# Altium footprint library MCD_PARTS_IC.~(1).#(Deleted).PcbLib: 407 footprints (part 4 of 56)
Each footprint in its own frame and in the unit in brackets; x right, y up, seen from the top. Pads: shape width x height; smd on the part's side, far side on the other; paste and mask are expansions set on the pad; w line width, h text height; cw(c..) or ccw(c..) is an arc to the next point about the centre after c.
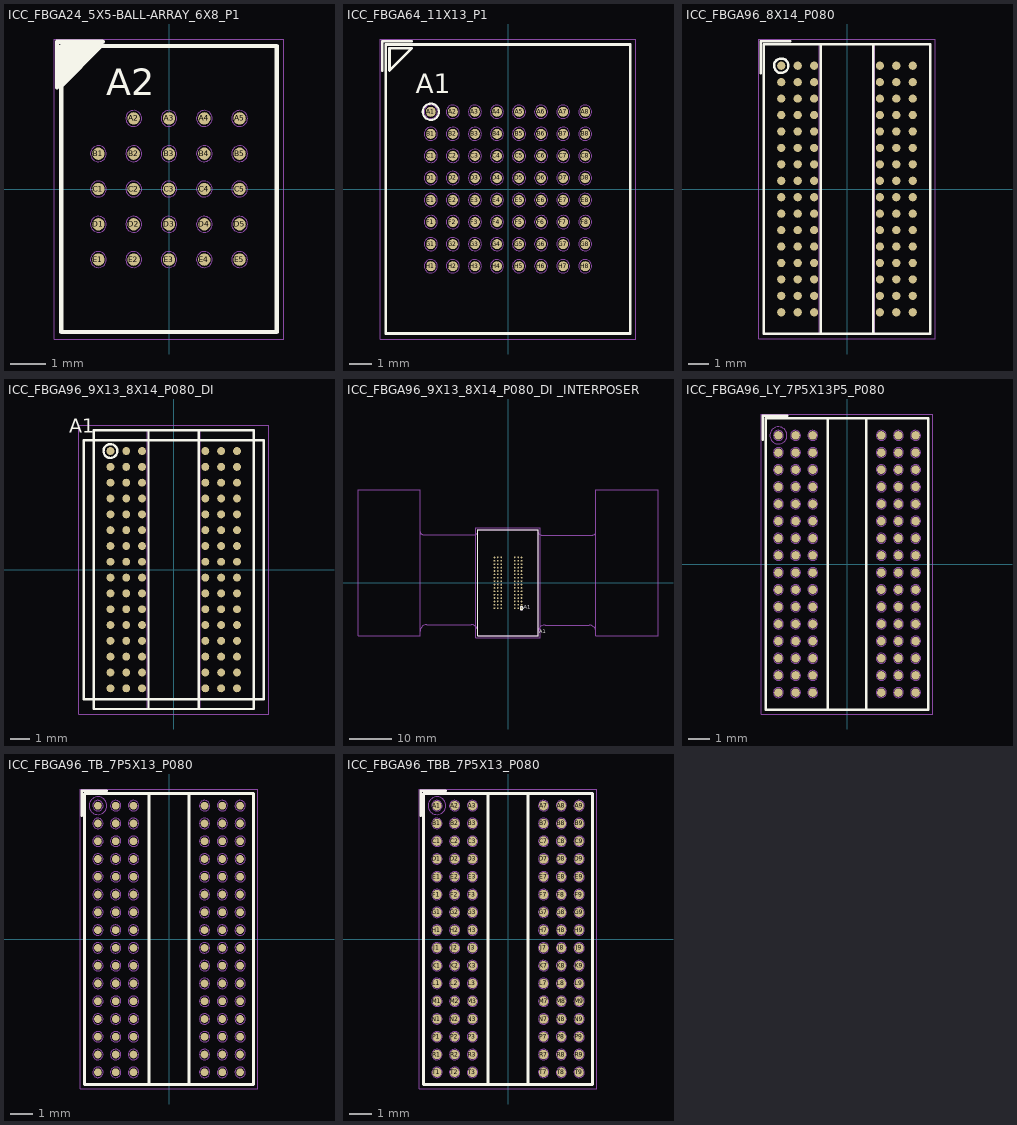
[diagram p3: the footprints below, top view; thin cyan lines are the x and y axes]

## ICC_FBGA24_5X5-BALL-ARRAY_6X8_P1 [mm] "MCD-01824"
height 1
pads (24):
  round 0.35 smd mask+0.05: A2(-1,2) A3(0,2) A4(1,2) A5(2,2) B1(-2,1) B2(-1,1) B3(0,1) B4(1,1) B5(2,1) C1(-2,0) C2(-1,0) C3(0,0) C4(1,0) C5(2,0) D1(-2,-1) D2(-1,-1) D3(0,-1) D4(1,-1) D5(2,-1) E1(-2,-2) E2(-1,-2) E3(0,-2) E4(1,-2) E5(2,-2)
Top Overlay:
  lines w0.12: -3.175,2.875 -3.175,4.175 -1.875,4.175 ; -3.05,2.925 -1.925,4.05 ; -3.05,3.025 -2.025,4.05 ; -3.05,3.175 -2.175,4.05 ; -3.05,3.325 -2.325,4.05 ; -3.05,3.475 -2.475,4.05 ; -3.05,3.625 -2.625,4.05 ; -3.05,3.775 -2.775,4.05 ; -3.05,3.9 -2.9,4.05 ; -3.05,-4.05 -3.05,4.05 3.05,4.05 3.05,-4.05 -3.05,-4.05
  text "A2" at -1.775,2.4 h1.3
M14-Top Assembly:
  circle w0.01: c-1,2 r0.225
  circle w0.01: c0,2 r0.225
  circle w0.01: c1,2 r0.225
  circle w0.01: c2,2 r0.225
  circle w0.01: c2,1 r0.225
  circle w0.01: c1,1 r0.225
  circle w0.01: c0,1 r0.225
  circle w0.01: c-1,1 r0.225
  circle w0.01: c-2,1 r0.225
  circle w0.01: c2,0 r0.225
  circle w0.01: c1,0 r0.225
  circle w0.01: c0,0 r0.225
  circle w0.01: c-1,0 r0.225
  circle w0.01: c-2,0 r0.225
  circle w0.01: c2,-1 r0.225
  circle w0.01: c1,-1 r0.225
  circle w0.01: c0,-1 r0.225
  circle w0.01: c-1,-1 r0.225
  circle w0.01: c-2,-1 r0.225
  circle w0.01: c2,-2 r0.225
  circle w0.01: c1,-2 r0.225
  circle w0.01: c0,-2 r0.225
  circle w0.01: c-1,-2 r0.225
  circle w0.01: c-2,-2 r0.225
  lines w0.01: -3.05,2.925 -1.925,4.05 -3.037,2.937 ; -3.05,-4.05 3.05,-4.05 3.05,4.05 -3.05,4.05 -3.05,-4.05
  text "'.Designator'" at -2,2.7 h0.75
  text "A2" at -1.424,1.795 h0.75
  text "E1" at -2.304,-2.205 h0.75
  text "D1" at -2.319,-1.205 h0.75
  text "C1" at -2.36,-0.205 h0.75
  text "B1" at -2.319,0.795 h0.75
  text "A5" at 1.601,1.795 h0.75
  text "A4" at 0.594,1.82 h0.75
  text "A3" at -0.424,1.795 h0.75
M16-Top Courtyard:
  lines w0.01: -3.25,-4.25 3.25,-4.25 3.25,4.25 -3.25,4.25 -3.25,-4.25
3D body "ICC_BGA24_5X5-BALL-ARRAY_6X8_P1.STEP": height 0.96, standoff -0.04, extent -3,-4 3,4
3D body: height 1, standoff 0, extent -3.055,-4.055 3.055,4.055

## ICC_FBGA64_11X13_P1 [mm] "IPC"
height 1.4
pads (64):
  round 0.45 smd mask+0.05: A1(-3.5,3.5) A2(-2.5,3.5) A3(-1.5,3.5) A4(-0.5,3.5) A5(0.5,3.5) A6(1.5,3.5) A7(2.5,3.5) A8(3.5,3.5) B1(-3.5,2.5) B2(-2.5,2.5) B3(-1.5,2.5) B4(-0.5,2.5) B5(0.5,2.5) B6(1.5,2.5) B7(2.5,2.5) B8(3.5,2.5) C1(-3.5,1.5) C2(-2.5,1.5) C3(-1.5,1.5) C4(-0.5,1.5) C5(0.5,1.5) C6(1.5,1.5) C7(2.5,1.5) C8(3.5,1.5) D1(-3.5,0.5) D2(-2.5,0.5) D3(-1.5,0.5) D4(-0.5,0.5) D5(0.5,0.5) D6(1.5,0.5) D7(2.5,0.5) D8(3.5,0.5) E1(-3.5,-0.5) E2(-2.5,-0.5) E3(-1.5,-0.5) E4(-0.5,-0.5) E5(0.5,-0.5) E6(1.5,-0.5) E7(2.5,-0.5) E8(3.5,-0.5) F1(-3.5,-1.5) F2(-2.5,-1.5) F3(-1.5,-1.5) F4(-0.5,-1.5) F5(0.5,-1.5) F6(1.5,-1.5) F7(2.5,-1.5) F8(3.5,-1.5) G1(-3.5,-2.5) G2(-2.5,-2.5) G3(-1.5,-2.5) G4(-0.5,-2.5) G5(0.5,-2.5) G6(1.5,-2.5) G7(2.5,-2.5) G8(3.5,-2.5) H1(-3.5,-3.5) H2(-2.5,-3.5) H3(-1.5,-3.5) H4(-0.5,-3.5) H5(0.5,-3.5) H6(1.5,-3.5) H7(2.5,-3.5) H8(3.5,-3.5)
Top Overlay:
  circle w0.1: c-3.5,3.5 r0.37
  lines w0.12: -5.7,5.375 -5.7,6.7 -4.375,6.7 ; -5.55,-6.55 5.55,-6.55 5.55,6.55 -5.55,6.55 -5.55,-6.55 ; -5.375,5.375 -4.375,6.375 -5.375,6.375 -5.375,5.375
  text "A1" at -4.175,4.05 h1.5
M14-Top Assembly:
  circle w0.01: c-3.5,-0.5 r0.3
  circle w0.01: c-2.5,-0.5 r0.3
  circle w0.01: c-1.5,-0.5 r0.3
  circle w0.01: c-0.5,-0.5 r0.3
  circle w0.01: c0.5,-0.5 r0.3
  circle w0.01: c1.5,-0.5 r0.3
  circle w0.01: c2.5,-0.5 r0.3
  circle w0.01: c3.5,-0.5 r0.3
  circle w0.01: c3.5,-1.5 r0.3
  circle w0.01: c2.5,-1.5 r0.3
  circle w0.01: c1.5,-1.5 r0.3
  circle w0.01: c0.5,-1.5 r0.3
  circle w0.01: c-0.5,-1.5 r0.3
  circle w0.01: c-1.5,-1.5 r0.3
  circle w0.01: c-2.5,-1.5 r0.3
  circle w0.01: c-3.5,-1.5 r0.3
  circle w0.01: c3.5,-2.5 r0.3
  circle w0.01: c2.5,-2.5 r0.3
  circle w0.01: c1.5,-2.5 r0.3
  circle w0.01: c0.5,-2.5 r0.3
  circle w0.01: c-0.5,-2.5 r0.3
  circle w0.01: c-1.5,-2.5 r0.3
  circle w0.01: c-2.5,-2.5 r0.3
  circle w0.01: c-3.5,-2.5 r0.3
  circle w0.01: c3.5,-3.5 r0.3
  circle w0.01: c2.5,-3.5 r0.3
  circle w0.01: c1.5,-3.5 r0.3
  circle w0.01: c0.5,-3.5 r0.3
  circle w0.01: c-0.5,-3.5 r0.3
  circle w0.01: c-1.5,-3.5 r0.3
  circle w0.01: c-2.5,-3.5 r0.3
  circle w0.01: c-3.5,-3.5 r0.3
  circle w0.01: c-3.5,0.5 r0.3
  circle w0.01: c-2.5,0.5 r0.3
  circle w0.01: c-1.5,0.5 r0.3
  circle w0.01: c-0.5,0.5 r0.3
  circle w0.01: c0.5,0.5 r0.3
  circle w0.01: c1.5,0.5 r0.3
  circle w0.01: c2.5,0.5 r0.3
  circle w0.01: c3.5,0.5 r0.3
  circle w0.01: c-3.5,1.5 r0.3
  circle w0.01: c-2.5,1.5 r0.3
  circle w0.01: c-1.5,1.5 r0.3
  circle w0.01: c-0.5,1.5 r0.3
  circle w0.01: c0.5,1.5 r0.3
  circle w0.01: c1.5,1.5 r0.3
  circle w0.01: c2.5,1.5 r0.3
  circle w0.01: c3.5,1.5 r0.3
  circle w0.01: c-3.5,2.5 r0.3
  circle w0.01: c-2.5,2.5 r0.3
  circle w0.01: c-1.5,2.5 r0.3
  circle w0.01: c-0.5,2.5 r0.3
  circle w0.01: c0.5,2.5 r0.3
  circle w0.01: c1.5,2.5 r0.3
  circle w0.01: c2.5,2.5 r0.3
  circle w0.01: c3.5,2.5 r0.3
  circle w0.01: c3.5,3.5 r0.3
  circle w0.01: c2.5,3.5 r0.3
  circle w0.01: c1.5,3.5 r0.3
  circle w0.01: c0.5,3.5 r0.3
  circle w0.01: c-0.5,3.5 r0.3
  circle w0.01: c-1.5,3.5 r0.3
  circle w0.01: c-2.5,3.5 r0.3
  circle w0.01: c-3.5,3.5 r0.3
  lines w0.01: -5.55,-6.55 5.55,-6.55 5.55,6.55 -5.55,6.55 -5.55,-6.55 ; -5.375,5.375 -4.375,6.375 -5.375,6.375 -5.375,5.375
  text "'.Designator'" at -2,-0.5 h0.75
  text "A1" at -4,3.25 h1
M16-Top Courtyard:
  lines w0.01: -5.8,-6.8 -5.8,6.8 5.8,6.8 5.8,-6.8 -5.8,-6.8
3D body: height 1.4, standoff 0, extent -5.55,-6.55 5.55,6.55
3D body: height 1.41, standoff 1.4, extent -4.847,5.251 -4.25,5.85
3D body "FBGA64_11x13_P1.STEP": height 1.4, standoff 0, extent -5.5,-6.5 5.5,6.5

## ICC_FBGA96_8X14_P080 [mm]
height 1.2
pads (96):
  round 0.4 smd mask+0.05: A1(-3.2,6) A2(-2.4,6) A3(-1.6,6) A7(1.6,6) A8(2.4,6) A9(3.2,6) B1(-3.2,5.2) B2(-2.4,5.2) B3(-1.6,5.2) B7(1.6,5.2) B8(2.4,5.2) B9(3.2,5.2) C1(-3.2,4.4) C2(-2.4,4.4) C3(-1.6,4.4) C7(1.6,4.4) C8(2.4,4.4) C9(3.2,4.4) D1(-3.2,3.6) D2(-2.4,3.6) D3(-1.6,3.6) D7(1.6,3.6) D8(2.4,3.6) D9(3.2,3.6) E1(-3.2,2.8) E2(-2.4,2.8) E3(-1.6,2.8) E7(1.6,2.8) E8(2.4,2.8) E9(3.2,2.8) F1(-3.2,2) F2(-2.4,2) F3(-1.6,2) F7(1.6,2) F8(2.4,2) F9(3.2,2) G1(-3.2,1.2) G2(-2.4,1.2) G3(-1.6,1.2) G7(1.6,1.2) G8(2.4,1.2) G9(3.2,1.2) H1(-3.2,0.4) H2(-2.4,0.4) H3(-1.6,0.4) H7(1.6,0.4) H8(2.4,0.4) H9(3.2,0.4) J1(-3.2,-0.4) J2(-2.4,-0.4) J3(-1.6,-0.4) J7(1.6,-0.4) J8(2.4,-0.4) J9(3.2,-0.4) K1(-3.2,-1.2) K2(-2.4,-1.2) K3(-1.6,-1.2) K7(1.6,-1.2) K8(2.4,-1.2) K9(3.2,-1.2) L1(-3.2,-2) L2(-2.4,-2) L3(-1.6,-2) L7(1.6,-2) L8(2.4,-2) L9(3.2,-2) M1(-3.2,-2.8) M2(-2.4,-2.8) M3(-1.6,-2.8) M7(1.6,-2.8) M8(2.4,-2.8) M9(3.2,-2.8) N1(-3.2,-3.6) N2(-2.4,-3.6) N3(-1.6,-3.6) N7(1.6,-3.6) N8(2.4,-3.6) N9(3.2,-3.6) P1(-3.2,-4.4) P2(-2.4,-4.4) P3(-1.6,-4.4) P7(1.6,-4.4) P8(2.4,-4.4) P9(3.2,-4.4) R1(-3.2,-5.2) R2(-2.4,-5.2) R3(-1.6,-5.2) R7(1.6,-5.2) R8(2.4,-5.2) R9(3.2,-5.2) T1(-3.2,-6) T2(-2.4,-6) T3(-1.6,-6) T7(1.6,-6) T8(2.4,-6) T9(3.2,-6)
Top Overlay:
  lines w0.12: -4.2,5.625 -4.2,7.2 -2.75,7.2 ; -2.851,6.023 ccw(c-3.2,6) -2.85,6 ; -1.275,-7.05 -1.275,7.05 ; 1.275,-7.05 1.275,7.05 ; -4.05,-7.05 4.05,-7.05 4.05,7.05 -4.05,7.05 -4.05,-7.05
M14-Top Assembly:
  circle w0.01: c-3.2,6 r0.35
  lines w0.01: -1.35,-7.05 -1.35,7.05 ; 1.35,-7.05 1.35,7.05 ; -4.05,-7.05 4.05,-7.05 4.05,7.05 -4.05,7.05 -4.05,-7.05
  text "'.Designator'" at -2,-0.5 h0.75
  text "A1" at -3.55,5.8 h0.75
M16-Top Courtyard:
  lines w0.01: -4.3,-7.3 -3.975,-7.3 4.3,-7.3 4.3,7.3 -4.3,7.3 -4.3,-7.3
3D body: height 1.2, standoff 0, extent -4.055,-7.055 4.055,7.055
3D body "VFBGA96.STEP": height 1, standoff 0, extent -4,-6.5 4,6.5

## ICC_FBGA96_9X13_8X14_P080_DI [mm]
height 1.2
pads (96):
  round 0.4 smd mask+0.05: A1(-3.2,6) A2(-2.4,6) A3(-1.6,6) A7(1.6,6) A8(2.4,6) A9(3.2,6) B1(-3.2,5.2) B2(-2.4,5.2) B3(-1.6,5.2) B7(1.6,5.2) B8(2.4,5.2) B9(3.2,5.2) C1(-3.2,4.4) C2(-2.4,4.4) C3(-1.6,4.4) C7(1.6,4.4) C8(2.4,4.4) C9(3.2,4.4) D1(-3.2,3.6) D2(-2.4,3.6) D3(-1.6,3.6) D7(1.6,3.6) D8(2.4,3.6) D9(3.2,3.6) E1(-3.2,2.8) E2(-2.4,2.8) E3(-1.6,2.8) E7(1.6,2.8) E8(2.4,2.8) E9(3.2,2.8) F1(-3.2,2) F2(-2.4,2) F3(-1.6,2) F7(1.6,2) F8(2.4,2) F9(3.2,2) G1(-3.2,1.2) G2(-2.4,1.2) G3(-1.6,1.2) G7(1.6,1.2) G8(2.4,1.2) G9(3.2,1.2) H1(-3.2,0.4) H2(-2.4,0.4) H3(-1.6,0.4) H7(1.6,0.4) H8(2.4,0.4) H9(3.2,0.4) J1(-3.2,-0.4) J2(-2.4,-0.4) J3(-1.6,-0.4) J7(1.6,-0.4) J8(2.4,-0.4) J9(3.2,-0.4) K1(-3.2,-1.2) K2(-2.4,-1.2) K3(-1.6,-1.2) K7(1.6,-1.2) K8(2.4,-1.2) K9(3.2,-1.2) L1(-3.2,-2) L2(-2.4,-2) L3(-1.6,-2) L7(1.6,-2) L8(2.4,-2) L9(3.2,-2) M1(-3.2,-2.8) M2(-2.4,-2.8) M3(-1.6,-2.8) M7(1.6,-2.8) M8(2.4,-2.8) M9(3.2,-2.8) N1(-3.2,-3.6) N2(-2.4,-3.6) N3(-1.6,-3.6) N7(1.6,-3.6) N8(2.4,-3.6) N9(3.2,-3.6) P1(-3.2,-4.4) P2(-2.4,-4.4) P3(-1.6,-4.4) P7(1.6,-4.4) P8(2.4,-4.4) P9(3.2,-4.4) R1(-3.2,-5.2) R2(-2.4,-5.2) R3(-1.6,-5.2) R7(1.6,-5.2) R8(2.4,-5.2) R9(3.2,-5.2) T1(-3.2,-6) T2(-2.4,-6) T3(-1.6,-6) T7(1.6,-6) T8(2.4,-6) T9(3.2,-6)
Top Overlay:
  lines w0.12: -2.851,6.023 ccw(c-3.2,6) -2.85,6 ; -1.275,-7.05 -1.275,7.05 ; 1.275,-7.05 1.275,7.05 ; -4.55,-6.55 4.55,-6.55 4.55,6.55 -4.55,6.55 -4.55,-6.55 ; -4.05,-7.05 -4.05,7.05 4.05,7.05 4.05,-7.05 -4.05,-7.05
  text "A1" at -5.275,6.675 h1.2
M14-Top Assembly:
  circle w0.01: c-3.2,6 r0.35
  lines w0.01: -1.35,-7.05 -1.35,7.05 ; 1.35,-7.05 1.35,7.05 ; -4.55,-6.55 4.55,-6.55 4.55,6.55 -4.55,6.55 -4.55,-6.55 ; -4.05,-7.05 -4.05,7.05 4.05,7.05 4.05,-7.05 -4.05,-7.05
  text "9 x 13" at -4.15,-6.5 h0.6
  text "8 x 14" at -4.025,6.625 h0.6
  text "A1" at -3.575,5.775 h0.75
  text "'.Designator'" at -2,-0.5 h0.75
M16-Top Courtyard:
  lines w0.01: -4.8,-7.3 -4.8,7.3 4.8,7.3 4.8,-7.3 -4.8,-7.3
3D body: height 1, standoff 0, extent -4.55,-6.55 4.55,6.55
3D body: height 1.2, standoff 0, extent -4.05,-7.05 4.05,7.05

## ICC_FBGA96_9X13_8X14_P080_DI _INTERPOSER [mm] "INTERPOSER DDR3 MCI BBLA96BC-A01_DIMS"
height 2
pads (96):
  round 0.4 smd mask+0.05: A1(3.2,-6) A2(2.4,-6) A3(1.6,-6) A7(-1.6,-6) A8(-2.4,-6) A9(-3.2,-6) B1(3.2,-5.2) B2(2.4,-5.2) B3(1.6,-5.2) B7(-1.6,-5.2) B8(-2.4,-5.2) B9(-3.2,-5.2) C1(3.2,-4.4) C2(2.4,-4.4) C3(1.6,-4.4) C7(-1.6,-4.4) C8(-2.4,-4.4) C9(-3.2,-4.4) D1(3.2,-3.6) D2(2.4,-3.6) D3(1.6,-3.6) D7(-1.6,-3.6) D8(-2.4,-3.6) D9(-3.2,-3.6) E1(3.2,-2.8) E2(2.4,-2.8) E3(1.6,-2.8) E7(-1.6,-2.8) E8(-2.4,-2.8) E9(-3.2,-2.8) F1(3.2,-2) F2(2.4,-2) F3(1.6,-2) F7(-1.6,-2) F8(-2.4,-2) F9(-3.2,-2) G1(3.2,-1.2) G2(2.4,-1.2) G3(1.6,-1.2) G7(-1.6,-1.2) G8(-2.4,-1.2) G9(-3.2,-1.2) H1(3.2,-0.4) H2(2.4,-0.4) H3(1.6,-0.4) H7(-1.6,-0.4) H8(-2.4,-0.4) H9(-3.2,-0.4) J1(3.2,0.4) J2(2.4,0.4) J3(1.6,0.4) J7(-1.6,0.4) J8(-2.4,0.4) J9(-3.2,0.4) K1(3.2,1.2) K2(2.4,1.2) K3(1.6,1.2) K7(-1.6,1.2) K8(-2.4,1.2) K9(-3.2,1.2) L1(3.2,2) L2(2.4,2) L3(1.6,2) L7(-1.6,2) L8(-2.4,2) L9(-3.2,2) M1(3.2,2.8) M2(2.4,2.8) M3(1.6,2.8) M7(-1.6,2.8) M8(-2.4,2.8) M9(-3.2,2.8) N1(3.2,3.6) N2(2.4,3.6) N3(1.6,3.6) N7(-1.6,3.6) N8(-2.4,3.6) N9(-3.2,3.6) P1(3.2,4.4) P2(2.4,4.4) P3(1.6,4.4) P7(-1.6,4.4) P8(-2.4,4.4) P9(-3.2,4.4) R1(3.2,5.2) R2(2.4,5.2) R3(1.6,5.2) R7(-1.6,5.2) R8(-2.4,5.2) R9(-3.2,5.2) T1(3.2,6) T2(2.4,6) T3(1.6,6) T7(-1.6,6) T8(-2.4,6) T9(-3.2,6)
Top Overlay:
  lines w0.12: 2.85,-6 cw(c3.2,-6) 2.851,-6.023 ; 7.15,-12.5 7.15,-12.475 7.15,12.5 -7.15,12.5 -7.15,-12.5 7.125,-12.5 7.15,-12.5 ; 7.15,-12.5 7.15,-12.5
  text "A1" at 7.4,-12.325 h1.5
  text "A1" at 3.75,-6.425 h1.5
M7-Top Info:
  lines w0.01: -20.75,-11.4 cw(c-19.2,-11.45) -19.15,-9.9 -8.65,-9.9 cw(c-8.7,-11.45) -7.15,-11.5 ; -20.75,12.1 ccw(c-20.05,12.1) -20.05,11.4 -8.25,11.4 ; -7.15,12.1 cw(c-7.85,12.1) -7.85,11.4 -8.25,11.4 ; 7.15,-11.5 cw(c8.7,-11.55) 8.75,-10 19.25,-10 cw(c19.2,-11.55) 20.75,-11.6 ; 7.15,12 ccw(c7.85,12) 7.85,11.3 19.65,11.3 ; 20.75,12 cw(c20.05,12) 20.05,11.3 19.65,11.3 ; -8.25,11.4 -8.25,11.4 ; 7.125,-12.5 7.15,-12.5 ; 7.125,-12.5 7.15,-12.5 ; 7.125,-12.5 -7.15,-12.5 -7.15,12.5 7.15,12.5 7.15,-12.475 ; 7.15,-12.5 7.15,-12.5 ; 7.15,-12.5 7.15,-12.475 ; 7.15,-12.5 7.15,-12.475 ; 7.15,-12.5 7.15,-12.5 ; 19.65,11.3 19.65,11.3 ; -35.45,-12.5 -20.75,-12.5 -20.75,22 -35.45,22 -35.45,-12.5 ; 20.75,-12.5 20.75,22 35.45,22 35.45,-12.5 20.75,-12.5
  text "FLEX / AREA" at 11.225,-2 h1.5
  text "FLEX / AREA" at -17,-2 h1.5
M14-Top Assembly:
  circle w0.01: c3.2,-6 r0.35
  lines w0.01: 7.125,-12.5 -7.15,-12.5 -7.15,12.5 7.15,12.5 7.15,-12.475
  text "A1" at 2.85,-6.2 h0.75
  text "'.Designator'" at -2,-0.5 h0.75
M16-Top Courtyard:
  lines w0.01: -7.65,-13 7.65,-13 7.65,13 -7.65,13 -7.65,-13
3D body: height 3.3, standoff 2.3, extent 7.15,-11.475 20.75,11.975
3D body: height 3.3, standoff 2.3, extent -20.75,-11.375 -7.15,12.075
3D body: height 3.6, standoff 2, extent -7.15,-12.5 7.15,12.5
3D body: height 3.6, standoff 2, extent 20.75,-12.5 35.45,22
3D body "VFBGA96.STEP": height 4.6, standoff 3.6, extent -4,-6.5 4,6.5
3D body: height 2, standoff 0, extent -7.15,-12.5 7.15,12.5
3D body: height 3.6, standoff 2, extent -35.45,-12.5 -20.75,22

## ICC_FBGA96_LY_7P5X13P5_P080 [mm] "MCD-02322"
height 1.2
pads (96):
  round 0.4 smd mask+0.05: A1(-3.2,6) A2(-2.4,6) A3(-1.6,6) A7(1.6,6) A8(2.4,6) A9(3.2,6) B1(-3.2,5.2) B2(-2.4,5.2) B3(-1.6,5.2) B7(1.6,5.2) B8(2.4,5.2) B9(3.2,5.2) C1(-3.2,4.4) C2(-2.4,4.4) C3(-1.6,4.4) C7(1.6,4.4) C8(2.4,4.4) C9(3.2,4.4) D1(-3.2,3.6) D2(-2.4,3.6) D3(-1.6,3.6) D7(1.6,3.6) D8(2.4,3.6) D9(3.2,3.6) E1(-3.2,2.8) E2(-2.4,2.8) E3(-1.6,2.8) E7(1.6,2.8) E8(2.4,2.8) E9(3.2,2.8) F1(-3.2,2) F2(-2.4,2) F3(-1.6,2) F7(1.6,2) F8(2.4,2) F9(3.2,2) G1(-3.2,1.2) G2(-2.4,1.2) G3(-1.6,1.2) G7(1.6,1.2) G8(2.4,1.2) G9(3.2,1.2) H1(-3.2,0.4) H2(-2.4,0.4) H3(-1.6,0.4) H7(1.6,0.4) H8(2.4,0.4) H9(3.2,0.4) J1(-3.2,-0.4) J2(-2.4,-0.4) J3(-1.6,-0.4) J7(1.6,-0.4) J8(2.4,-0.4) J9(3.2,-0.4) K1(-3.2,-1.2) K2(-2.4,-1.2) K3(-1.6,-1.2) K7(1.6,-1.2) K8(2.4,-1.2) K9(3.2,-1.2) L1(-3.2,-2) L2(-2.4,-2) L3(-1.6,-2) L7(1.6,-2) L8(2.4,-2) L9(3.2,-2) M1(-3.2,-2.8) M2(-2.4,-2.8) M3(-1.6,-2.8) M7(1.6,-2.8) M8(2.4,-2.8) M9(3.2,-2.8) N1(-3.2,-3.6) N2(-2.4,-3.6) N3(-1.6,-3.6) N7(1.6,-3.6) N8(2.4,-3.6) N9(3.2,-3.6) P1(-3.2,-4.4) P2(-2.4,-4.4) P3(-1.6,-4.4) P7(1.6,-4.4) P8(2.4,-4.4) P9(3.2,-4.4) R1(-3.2,-5.2) R2(-2.4,-5.2) R3(-1.6,-5.2) R7(1.6,-5.2) R8(2.4,-5.2) R9(3.2,-5.2) T1(-3.2,-6) T2(-2.4,-6) T3(-1.6,-6) T7(1.6,-6) T8(2.4,-6) T9(3.2,-6)
Top Overlay:
  lines w0.12: -3.925,5.8 -3.925,6.925 -2.8,6.925 ; -0.9,-6.8 -0.9,6.8 ; 0.9,-6.8 0.9,6.8 ; -3.8,-6.8 3.8,-6.8 3.8,6.8 -3.8,6.8 -3.8,-6.8
M14-Top Assembly:
  circle w0.01: c-3.2,6 r0.235
  circle w0.01: c-2.4,6 r0.235
  circle w0.01: c-1.6,6 r0.235
  circle w0.01: c1.6,6 r0.235
  circle w0.01: c2.4,6 r0.235
  circle w0.01: c3.2,6 r0.235
  circle w0.01: c-3.2,5.2 r0.235
  circle w0.01: c-2.4,5.2 r0.235
  circle w0.01: c-1.6,5.2 r0.235
  circle w0.01: c1.6,5.2 r0.235
  circle w0.01: c2.4,5.2 r0.235
  circle w0.01: c3.2,5.2 r0.235
  circle w0.01: c-3.2,4.4 r0.235
  circle w0.01: c-2.4,4.4 r0.235
  circle w0.01: c-1.6,4.4 r0.235
  circle w0.01: c1.6,4.4 r0.235
  circle w0.01: c2.4,4.4 r0.235
  circle w0.01: c3.2,4.4 r0.235
  circle w0.01: c-3.2,3.6 r0.235
  circle w0.01: c-2.4,3.6 r0.235
  circle w0.01: c-1.6,3.6 r0.235
  circle w0.01: c1.6,3.6 r0.235
  circle w0.01: c2.4,3.6 r0.235
  circle w0.01: c3.2,3.6 r0.235
  circle w0.01: c-3.2,2.8 r0.235
  circle w0.01: c-2.4,2.8 r0.235
  circle w0.01: c-1.6,2.8 r0.235
  circle w0.01: c1.6,2.8 r0.235
  circle w0.01: c2.4,2.8 r0.235
  circle w0.01: c3.2,2.8 r0.235
  circle w0.01: c-3.2,2 r0.235
  circle w0.01: c-2.4,2 r0.235
  circle w0.01: c-1.6,2 r0.235
  circle w0.01: c1.6,2 r0.235
  circle w0.01: c2.4,2 r0.235
  circle w0.01: c3.2,2 r0.235
  circle w0.01: c-3.2,1.2 r0.235
  circle w0.01: c-2.4,1.2 r0.235
  circle w0.01: c-1.6,1.2 r0.235
  circle w0.01: c1.6,1.2 r0.235
  circle w0.01: c2.4,1.2 r0.235
  circle w0.01: c3.2,1.2 r0.235
  circle w0.01: c-3.2,0.4 r0.235
  circle w0.01: c-2.4,0.4 r0.235
  circle w0.01: c-1.6,0.4 r0.235
  circle w0.01: c1.6,0.4 r0.235
  circle w0.01: c2.4,0.4 r0.235
  circle w0.01: c3.2,0.4 r0.235
  circle w0.01: c-3.2,-6 r0.235
  circle w0.01: c-2.4,-6 r0.235
  circle w0.01: c-1.6,-6 r0.235
  circle w0.01: c1.6,-6 r0.235
  circle w0.01: c2.4,-6 r0.235
  circle w0.01: c3.2,-6 r0.235
  circle w0.01: c-3.2,-5.2 r0.235
  circle w0.01: c-2.4,-5.2 r0.235
  circle w0.01: c-1.6,-5.2 r0.235
  circle w0.01: c1.6,-5.2 r0.235
  circle w0.01: c2.4,-5.2 r0.235
  circle w0.01: c3.2,-5.2 r0.235
  circle w0.01: c-3.2,-4.4 r0.235
  circle w0.01: c-2.4,-4.4 r0.235
  circle w0.01: c-1.6,-4.4 r0.235
  circle w0.01: c1.6,-4.4 r0.235
  circle w0.01: c2.4,-4.4 r0.235
  circle w0.01: c3.2,-4.4 r0.235
  circle w0.01: c-3.2,-3.6 r0.235
  circle w0.01: c-2.4,-3.6 r0.235
  circle w0.01: c-1.6,-3.6 r0.235
  circle w0.01: c1.6,-3.6 r0.235
  circle w0.01: c2.4,-3.6 r0.235
  circle w0.01: c3.2,-3.6 r0.235
  circle w0.01: c-3.2,-2.8 r0.235
  circle w0.01: c-2.4,-2.8 r0.235
  circle w0.01: c-1.6,-2.8 r0.235
  circle w0.01: c1.6,-2.8 r0.235
  circle w0.01: c2.4,-2.8 r0.235
  circle w0.01: c3.2,-2.8 r0.235
  circle w0.01: c-3.2,-2 r0.235
  circle w0.01: c-2.4,-2 r0.235
  circle w0.01: c-1.6,-2 r0.235
  circle w0.01: c1.6,-2 r0.235
  circle w0.01: c2.4,-2 r0.235
  circle w0.01: c3.2,-2 r0.235
  circle w0.01: c-3.2,-1.2 r0.235
  circle w0.01: c-2.4,-1.2 r0.235
  circle w0.01: c-1.6,-1.2 r0.235
  circle w0.01: c1.6,-1.2 r0.235
  circle w0.01: c2.4,-1.2 r0.235
  circle w0.01: c3.2,-1.2 r0.235
  circle w0.01: c-3.2,-0.4 r0.235
  circle w0.01: c-2.4,-0.4 r0.235
  circle w0.01: c-1.6,-0.4 r0.235
  circle w0.01: c1.6,-0.4 r0.235
  circle w0.01: c2.4,-0.4 r0.235
  circle w0.01: c3.2,-0.4 r0.235
  circle w0.01: c-3.2,6 r0.4
  lines w0.01: -0.9,-6.8 -0.9,6.8 ; 0.9,-6.8 0.9,6.8 ; -3.8,-6.8 3.8,-6.8 3.8,6.8 -3.8,6.8 -3.8,-6.8
  text "A1" at -3.55,5.8 h0.75
  text "'.Designator'" at -2,-0.5 h0.75
M16-Top Courtyard:
  lines w0.01: -4,-7 4,-7 4,7 -4,7 -4,-7
3D body: height 1.2, standoff 0.28, extent -3.8,-6.8 3.8,6.8
3D body: height 0.36, standoff -0.04, extent 3.001,-6.197 3.4,-5.803
3D body: height 0.36, standoff -0.04, extent 2.201,-6.197 2.6,-5.803
3D body: height 0.36, standoff -0.04, extent 1.401,-6.197 1.8,-5.803
3D body: height 0.36, standoff -0.04, extent -1.799,-6.197 -1.4,-5.803
3D body: height 0.36, standoff -0.04, extent -2.599,-6.197 -2.2,-5.803
3D body: height 0.36, standoff -0.04, extent -3.399,-6.197 -3,-5.803
3D body: height 0.36, standoff -0.04, extent 3.001,-5.397 3.4,-5.003
3D body: height 0.36, standoff -0.04, extent 2.201,-5.397 2.6,-5.003
3D body: height 0.36, standoff -0.04, extent 1.401,-5.397 1.8,-5.003
3D body: height 0.36, standoff -0.04, extent -1.799,-5.397 -1.4,-5.003
3D body: height 0.36, standoff -0.04, extent -2.599,-5.397 -2.2,-5.003
3D body: height 0.36, standoff -0.04, extent -3.399,-5.397 -3,-5.003
3D body: height 0.36, standoff -0.04, extent 3.001,-4.597 3.4,-4.203
3D body: height 0.36, standoff -0.04, extent 2.201,-4.597 2.6,-4.203
3D body: height 0.36, standoff -0.04, extent 1.401,-4.597 1.8,-4.203
3D body: height 0.36, standoff -0.04, extent -1.799,-4.597 -1.4,-4.203
3D body: height 0.36, standoff -0.04, extent -2.599,-4.597 -2.2,-4.203
3D body: height 0.36, standoff -0.04, extent -3.399,-4.597 -3,-4.203
3D body: height 0.36, standoff -0.04, extent 3.001,-3.797 3.4,-3.403
3D body: height 0.36, standoff -0.04, extent 2.201,-3.797 2.6,-3.403
3D body: height 0.36, standoff -0.04, extent 1.401,-3.797 1.8,-3.403
3D body: height 0.36, standoff -0.04, extent -1.799,-3.797 -1.4,-3.403
3D body: height 0.36, standoff -0.04, extent -2.599,-3.797 -2.2,-3.403
3D body: height 0.36, standoff -0.04, extent -3.399,-3.797 -3,-3.403
3D body: height 0.36, standoff -0.04, extent 3.001,-2.997 3.4,-2.603
3D body: height 0.36, standoff -0.04, extent 2.201,-2.997 2.6,-2.603
3D body: height 0.36, standoff -0.04, extent 1.401,-2.997 1.8,-2.603
3D body: height 0.36, standoff -0.04, extent -1.799,-2.997 -1.4,-2.603
3D body: height 0.36, standoff -0.04, extent -2.599,-2.997 -2.2,-2.603
3D body: height 0.36, standoff -0.04, extent -3.399,-2.997 -3,-2.603
3D body: height 0.36, standoff -0.04, extent 3.001,-2.197 3.4,-1.803
3D body: height 0.36, standoff -0.04, extent 2.201,-2.197 2.6,-1.803
3D body: height 0.36, standoff -0.04, extent 1.401,-2.197 1.8,-1.803
3D body: height 0.36, standoff -0.04, extent -1.799,-2.197 -1.4,-1.803
3D body: height 0.36, standoff -0.04, extent -2.599,-2.197 -2.2,-1.803
3D body: height 0.36, standoff -0.04, extent -3.399,-2.197 -3,-1.803
3D body: height 0.36, standoff -0.04, extent 3.001,-1.397 3.4,-1.003
3D body: height 0.36, standoff -0.04, extent 2.201,-1.397 2.6,-1.003
3D body: height 0.36, standoff -0.04, extent 1.401,-1.397 1.8,-1.003
3D body: height 0.36, standoff -0.04, extent -1.799,-1.397 -1.4,-1.003
3D body: height 0.36, standoff -0.04, extent -2.599,-1.397 -2.2,-1.003
3D body: height 0.36, standoff -0.04, extent -3.399,-1.397 -3,-1.003
3D body: height 0.36, standoff -0.04, extent 3.001,-0.597 3.4,-0.203
3D body: height 0.36, standoff -0.04, extent 2.201,-0.597 2.6,-0.203
3D body: height 0.36, standoff -0.04, extent 1.401,-0.597 1.8,-0.203
3D body: height 0.36, standoff -0.04, extent -1.799,-0.597 -1.4,-0.203
3D body: height 0.36, standoff -0.04, extent -2.599,-0.597 -2.2,-0.203
3D body: height 0.36, standoff -0.04, extent -3.399,-0.597 -3,-0.203
3D body: height 0.36, standoff -0.04, extent 3.001,0.203 3.4,0.597
3D body: height 0.36, standoff -0.04, extent 2.201,0.203 2.6,0.597
3D body: height 0.36, standoff -0.04, extent 1.401,0.203 1.8,0.597
3D body: height 0.36, standoff -0.04, extent -1.799,0.203 -1.4,0.597
3D body: height 0.36, standoff -0.04, extent -2.599,0.203 -2.2,0.597
3D body: height 0.36, standoff -0.04, extent -3.399,0.203 -3,0.597
3D body: height 0.36, standoff -0.04, extent 3.001,1.003 3.4,1.397
3D body: height 0.36, standoff -0.04, extent 2.201,1.003 2.6,1.397
3D body: height 0.36, standoff -0.04, extent 1.401,1.003 1.8,1.397
3D body: height 0.36, standoff -0.04, extent -1.799,1.003 -1.4,1.397
3D body: height 0.36, standoff -0.04, extent -2.599,1.003 -2.2,1.397
3D body: height 0.36, standoff -0.04, extent -3.399,1.003 -3,1.397
3D body: height 0.36, standoff -0.04, extent 3.001,1.803 3.4,2.197
3D body: height 0.36, standoff -0.04, extent 2.201,1.803 2.6,2.197
3D body: height 0.36, standoff -0.04, extent 1.401,1.803 1.8,2.197
3D body: height 0.36, standoff -0.04, extent -1.799,1.803 -1.4,2.197
3D body: height 0.36, standoff -0.04, extent -2.599,1.803 -2.2,2.197
3D body: height 0.36, standoff -0.04, extent -3.399,1.803 -3,2.197
3D body: height 0.36, standoff -0.04, extent 3.001,2.603 3.4,2.997
3D body: height 0.36, standoff -0.04, extent 2.201,2.603 2.6,2.997
3D body: height 0.36, standoff -0.04, extent 1.401,2.603 1.8,2.997
3D body: height 0.36, standoff -0.04, extent -1.799,2.603 -1.4,2.997
3D body: height 0.36, standoff -0.04, extent -2.599,2.603 -2.2,2.997
3D body: height 0.36, standoff -0.04, extent -3.399,2.603 -3,2.997
3D body: height 0.36, standoff -0.04, extent 3.001,3.403 3.4,3.797
3D body: height 0.36, standoff -0.04, extent 2.201,3.403 2.6,3.797
3D body: height 0.36, standoff -0.04, extent 1.401,3.403 1.8,3.797
3D body: height 0.36, standoff -0.04, extent -1.799,3.403 -1.4,3.797
3D body: height 0.36, standoff -0.04, extent -2.599,3.403 -2.2,3.797
3D body: height 0.36, standoff -0.04, extent -3.399,3.403 -3,3.797
3D body: height 0.36, standoff -0.04, extent 3.001,4.203 3.4,4.597
3D body: height 0.36, standoff -0.04, extent 2.201,4.203 2.6,4.597
3D body: height 0.36, standoff -0.04, extent 1.401,4.203 1.8,4.597
3D body: height 0.36, standoff -0.04, extent -1.799,4.203 -1.4,4.597
3D body: height 0.36, standoff -0.04, extent -2.599,4.203 -2.2,4.597
3D body: height 0.36, standoff -0.04, extent -3.399,4.203 -3,4.597
3D body: height 0.36, standoff -0.04, extent 3.001,5.003 3.4,5.397
3D body: height 0.36, standoff -0.04, extent 2.201,5.003 2.6,5.397
3D body: height 0.36, standoff -0.04, extent 1.401,5.003 1.8,5.397
3D body: height 0.36, standoff -0.04, extent -1.799,5.003 -1.4,5.397
3D body: height 0.36, standoff -0.04, extent -2.599,5.003 -2.2,5.397
3D body: height 0.36, standoff -0.04, extent -3.399,5.003 -3,5.397
3D body: height 0.36, standoff -0.04, extent 3.001,5.803 3.4,6.197
3D body: height 0.36, standoff -0.04, extent 2.201,5.803 2.6,6.197
3D body: height 0.36, standoff -0.04, extent 1.401,5.803 1.8,6.197
3D body: height 0.36, standoff -0.04, extent -1.799,5.803 -1.4,6.197
3D body: height 0.36, standoff -0.04, extent -2.599,5.803 -2.2,6.197
3D body: height 0.36, standoff -0.04, extent -3.399,5.803 -3,6.197
3D body: height 0.28, standoff 0.12, extent -0.9,-6.8 0.9,6.8
3D body: height 1.21, standoff 1.2, extent -3.497,5.701 -2.9,6.3

## ICC_FBGA96_TB_7P5X13_P080 [mm] "MCD-03523"
height 1.2
pads (96):
  round 0.35 smd mask+0.05: A1(-3.2,6) A2(-2.4,6) A3(-1.6,6) A7(1.6,6) A8(2.4,6) A9(3.2,6) B1(-3.2,5.2) B2(-2.4,5.2) B3(-1.6,5.2) B7(1.6,5.2) B8(2.4,5.2) B9(3.2,5.2) C1(-3.2,4.4) C2(-2.4,4.4) C3(-1.6,4.4) C7(1.6,4.4) C8(2.4,4.4) C9(3.2,4.4) D1(-3.2,3.6) D2(-2.4,3.6) D3(-1.6,3.6) D7(1.6,3.6) D8(2.4,3.6) D9(3.2,3.6) E1(-3.2,2.8) E2(-2.4,2.8) E3(-1.6,2.8) E7(1.6,2.8) E8(2.4,2.8) E9(3.2,2.8) F1(-3.2,2) F2(-2.4,2) F3(-1.6,2) F7(1.6,2) F8(2.4,2) F9(3.2,2) G1(-3.2,1.2) G2(-2.4,1.2) G3(-1.6,1.2) G7(1.6,1.2) G8(2.4,1.2) G9(3.2,1.2) H1(-3.2,0.4) H2(-2.4,0.4) H3(-1.6,0.4) H7(1.6,0.4) H8(2.4,0.4) H9(3.2,0.4) J1(-3.2,-0.4) J2(-2.4,-0.4) J3(-1.6,-0.4) J7(1.6,-0.4) J8(2.4,-0.4) J9(3.2,-0.4) K1(-3.2,-1.2) K2(-2.4,-1.2) K3(-1.6,-1.2) K7(1.6,-1.2) K8(2.4,-1.2) K9(3.2,-1.2) L1(-3.2,-2) L2(-2.4,-2) L3(-1.6,-2) L7(1.6,-2) L8(2.4,-2) L9(3.2,-2) M1(-3.2,-2.8) M2(-2.4,-2.8) M3(-1.6,-2.8) M7(1.6,-2.8) M8(2.4,-2.8) M9(3.2,-2.8) N1(-3.2,-3.6) N2(-2.4,-3.6) N3(-1.6,-3.6) N7(1.6,-3.6) N8(2.4,-3.6) N9(3.2,-3.6) P1(-3.2,-4.4) P2(-2.4,-4.4) P3(-1.6,-4.4) P7(1.6,-4.4) P8(2.4,-4.4) P9(3.2,-4.4) R1(-3.2,-5.2) R2(-2.4,-5.2) R3(-1.6,-5.2) R7(1.6,-5.2) R8(2.4,-5.2) R9(3.2,-5.2) T1(-3.2,-6) T2(-2.4,-6) T3(-1.6,-6) T7(1.6,-6) T8(2.4,-6) T9(3.2,-6)
Top Overlay:
  lines w0.12: -3.925,5.55 -3.925,6.675 -2.8,6.675 ; -0.9,-6.55 -0.9,6.55 ; 0.9,-6.55 0.9,6.55 ; -3.8,-6.55 -3.8,6.55 3.8,6.55 3.8,-6.55 -3.8,-6.55
M14-Top Assembly:
  circle w0.01: c-3.2,6 r0.4
  circle w0.01: c3.2,-0.4 r0.235
  circle w0.01: c2.4,-0.4 r0.235
  circle w0.01: c1.6,-0.4 r0.235
  circle w0.01: c-1.6,-0.4 r0.235
  circle w0.01: c-2.4,-0.4 r0.235
  circle w0.01: c-3.2,-0.4 r0.235
  circle w0.01: c3.2,-1.2 r0.235
  circle w0.01: c2.4,-1.2 r0.235
  circle w0.01: c1.6,-1.2 r0.235
  circle w0.01: c-1.6,-1.2 r0.235
  circle w0.01: c-2.4,-1.2 r0.235
  circle w0.01: c-3.2,-1.2 r0.235
  circle w0.01: c3.2,-2 r0.235
  circle w0.01: c2.4,-2 r0.235
  circle w0.01: c1.6,-2 r0.235
  circle w0.01: c-1.6,-2 r0.235
  circle w0.01: c-2.4,-2 r0.235
  circle w0.01: c-3.2,-2 r0.235
  circle w0.01: c3.2,-2.8 r0.235
  circle w0.01: c2.4,-2.8 r0.235
  circle w0.01: c1.6,-2.8 r0.235
  circle w0.01: c-1.6,-2.8 r0.235
  circle w0.01: c-2.4,-2.8 r0.235
  circle w0.01: c-3.2,-2.8 r0.235
  circle w0.01: c3.2,-3.6 r0.235
  circle w0.01: c2.4,-3.6 r0.235
  circle w0.01: c1.6,-3.6 r0.235
  circle w0.01: c-1.6,-3.6 r0.235
  circle w0.01: c-2.4,-3.6 r0.235
  circle w0.01: c-3.2,-3.6 r0.235
  circle w0.01: c3.2,-4.4 r0.235
  circle w0.01: c2.4,-4.4 r0.235
  circle w0.01: c1.6,-4.4 r0.235
  circle w0.01: c-1.6,-4.4 r0.235
  circle w0.01: c-2.4,-4.4 r0.235
  circle w0.01: c-3.2,-4.4 r0.235
  circle w0.01: c3.2,-5.2 r0.235
  circle w0.01: c2.4,-5.2 r0.235
  circle w0.01: c1.6,-5.2 r0.235
  circle w0.01: c-1.6,-5.2 r0.235
  circle w0.01: c-2.4,-5.2 r0.235
  circle w0.01: c-3.2,-5.2 r0.235
  circle w0.01: c3.2,-6 r0.235
  circle w0.01: c2.4,-6 r0.235
  circle w0.01: c1.6,-6 r0.235
  circle w0.01: c-1.6,-6 r0.235
  circle w0.01: c-2.4,-6 r0.235
  circle w0.01: c-3.2,-6 r0.235
  circle w0.01: c3.2,0.4 r0.235
  circle w0.01: c2.4,0.4 r0.235
  circle w0.01: c1.6,0.4 r0.235
  circle w0.01: c-1.6,0.4 r0.235
  circle w0.01: c-2.4,0.4 r0.235
  circle w0.01: c-3.2,0.4 r0.235
  circle w0.01: c3.2,1.2 r0.235
  circle w0.01: c2.4,1.2 r0.235
  circle w0.01: c1.6,1.2 r0.235
  circle w0.01: c-1.6,1.2 r0.235
  circle w0.01: c-2.4,1.2 r0.235
  circle w0.01: c-3.2,1.2 r0.235
  circle w0.01: c3.2,2 r0.235
  circle w0.01: c2.4,2 r0.235
  circle w0.01: c1.6,2 r0.235
  circle w0.01: c-1.6,2 r0.235
  circle w0.01: c-2.4,2 r0.235
  circle w0.01: c-3.2,2 r0.235
  circle w0.01: c3.2,2.8 r0.235
  circle w0.01: c2.4,2.8 r0.235
  circle w0.01: c1.6,2.8 r0.235
  circle w0.01: c-1.6,2.8 r0.235
  circle w0.01: c-2.4,2.8 r0.235
  circle w0.01: c-3.2,2.8 r0.235
  circle w0.01: c3.2,3.6 r0.235
  circle w0.01: c2.4,3.6 r0.235
  circle w0.01: c1.6,3.6 r0.235
  circle w0.01: c-1.6,3.6 r0.235
  circle w0.01: c-2.4,3.6 r0.235
  circle w0.01: c-3.2,3.6 r0.235
  circle w0.01: c3.2,4.4 r0.235
  circle w0.01: c2.4,4.4 r0.235
  circle w0.01: c1.6,4.4 r0.235
  circle w0.01: c-1.6,4.4 r0.235
  circle w0.01: c-2.4,4.4 r0.235
  circle w0.01: c-3.2,4.4 r0.235
  circle w0.01: c3.2,5.2 r0.235
  circle w0.01: c2.4,5.2 r0.235
  circle w0.01: c1.6,5.2 r0.235
  circle w0.01: c-1.6,5.2 r0.235
  circle w0.01: c-2.4,5.2 r0.235
  circle w0.01: c-3.2,5.2 r0.235
  circle w0.01: c3.2,6 r0.235
  circle w0.01: c2.4,6 r0.235
  circle w0.01: c1.6,6 r0.235
  circle w0.01: c-1.6,6 r0.235
  circle w0.01: c-2.4,6 r0.235
  circle w0.01: c-3.2,6 r0.235
  lines w0.01: -0.9,-6.55 -0.9,6.55 ; 0.9,-6.55 0.9,6.55 ; -3.8,-6.55 -3.8,6.55 3.8,6.55 3.8,-6.55 -3.8,-6.55
  text "'.Designator'" at -2,-0.5 h0.75
  text "A1" at -3.55,5.8 h0.75
M16-Top Courtyard:
  lines w0.01: -4,-6.75 -4,6.75 4,6.75 4,-6.75 -4,-6.75
3D body: height 1.21, standoff 1.2, extent -3.497,5.701 -2.9,6.3
3D body: height 0.28, standoff 0.12, extent -0.9,-6.55 0.9,6.55
3D body: height 0.36, standoff -0.04, extent -3.399,5.803 -3,6.197
3D body: height 0.36, standoff -0.04, extent -2.599,5.803 -2.2,6.197
3D body: height 0.36, standoff -0.04, extent -1.799,5.803 -1.4,6.197
3D body: height 0.36, standoff -0.04, extent 1.401,5.803 1.8,6.197
3D body: height 0.36, standoff -0.04, extent 2.201,5.803 2.6,6.197
3D body: height 0.36, standoff -0.04, extent 3.001,5.803 3.4,6.197
3D body: height 0.36, standoff -0.04, extent -3.399,5.003 -3,5.397
3D body: height 0.36, standoff -0.04, extent -2.599,5.003 -2.2,5.397
3D body: height 0.36, standoff -0.04, extent -1.799,5.003 -1.4,5.397
3D body: height 0.36, standoff -0.04, extent 1.401,5.003 1.8,5.397
3D body: height 0.36, standoff -0.04, extent 2.201,5.003 2.6,5.397
3D body: height 0.36, standoff -0.04, extent 3.001,5.003 3.4,5.397
3D body: height 0.36, standoff -0.04, extent -3.399,4.203 -3,4.597
3D body: height 0.36, standoff -0.04, extent -2.599,4.203 -2.2,4.597
3D body: height 0.36, standoff -0.04, extent -1.799,4.203 -1.4,4.597
3D body: height 0.36, standoff -0.04, extent 1.401,4.203 1.8,4.597
3D body: height 0.36, standoff -0.04, extent 2.201,4.203 2.6,4.597
3D body: height 0.36, standoff -0.04, extent 3.001,4.203 3.4,4.597
3D body: height 0.36, standoff -0.04, extent -3.399,3.403 -3,3.797
3D body: height 0.36, standoff -0.04, extent -2.599,3.403 -2.2,3.797
3D body: height 0.36, standoff -0.04, extent -1.799,3.403 -1.4,3.797
3D body: height 0.36, standoff -0.04, extent 1.401,3.403 1.8,3.797
3D body: height 0.36, standoff -0.04, extent 2.201,3.403 2.6,3.797
3D body: height 0.36, standoff -0.04, extent 3.001,3.403 3.4,3.797
3D body: height 0.36, standoff -0.04, extent -3.399,2.603 -3,2.997
3D body: height 0.36, standoff -0.04, extent -2.599,2.603 -2.2,2.997
3D body: height 0.36, standoff -0.04, extent -1.799,2.603 -1.4,2.997
3D body: height 0.36, standoff -0.04, extent 1.401,2.603 1.8,2.997
3D body: height 0.36, standoff -0.04, extent 2.201,2.603 2.6,2.997
3D body: height 0.36, standoff -0.04, extent 3.001,2.603 3.4,2.997
3D body: height 0.36, standoff -0.04, extent -3.399,1.803 -3,2.197
3D body: height 0.36, standoff -0.04, extent -2.599,1.803 -2.2,2.197
3D body: height 0.36, standoff -0.04, extent -1.799,1.803 -1.4,2.197
3D body: height 0.36, standoff -0.04, extent 1.401,1.803 1.8,2.197
3D body: height 0.36, standoff -0.04, extent 2.201,1.803 2.6,2.197
3D body: height 0.36, standoff -0.04, extent 3.001,1.803 3.4,2.197
3D body: height 0.36, standoff -0.04, extent -3.399,1.003 -3,1.397
3D body: height 0.36, standoff -0.04, extent -2.599,1.003 -2.2,1.397
3D body: height 0.36, standoff -0.04, extent -1.799,1.003 -1.4,1.397
3D body: height 0.36, standoff -0.04, extent 1.401,1.003 1.8,1.397
3D body: height 0.36, standoff -0.04, extent 2.201,1.003 2.6,1.397
3D body: height 0.36, standoff -0.04, extent 3.001,1.003 3.4,1.397
3D body: height 0.36, standoff -0.04, extent -3.399,0.203 -3,0.597
3D body: height 0.36, standoff -0.04, extent -2.599,0.203 -2.2,0.597
3D body: height 0.36, standoff -0.04, extent -1.799,0.203 -1.4,0.597
3D body: height 0.36, standoff -0.04, extent 1.401,0.203 1.8,0.597
3D body: height 0.36, standoff -0.04, extent 2.201,0.203 2.6,0.597
3D body: height 0.36, standoff -0.04, extent 3.001,0.203 3.4,0.597
3D body: height 0.36, standoff -0.04, extent -3.399,-0.597 -3,-0.203
3D body: height 0.36, standoff -0.04, extent -2.599,-0.597 -2.2,-0.203
3D body: height 0.36, standoff -0.04, extent -1.799,-0.597 -1.4,-0.203
3D body: height 0.36, standoff -0.04, extent 1.401,-0.597 1.8,-0.203
3D body: height 0.36, standoff -0.04, extent 2.201,-0.597 2.6,-0.203
3D body: height 0.36, standoff -0.04, extent 3.001,-0.597 3.4,-0.203
3D body: height 0.36, standoff -0.04, extent -3.399,-1.397 -3,-1.003
3D body: height 0.36, standoff -0.04, extent -2.599,-1.397 -2.2,-1.003
3D body: height 0.36, standoff -0.04, extent -1.799,-1.397 -1.4,-1.003
3D body: height 0.36, standoff -0.04, extent 1.401,-1.397 1.8,-1.003
3D body: height 0.36, standoff -0.04, extent 2.201,-1.397 2.6,-1.003
3D body: height 0.36, standoff -0.04, extent 3.001,-1.397 3.4,-1.003
3D body: height 0.36, standoff -0.04, extent -3.399,-2.197 -3,-1.803
3D body: height 0.36, standoff -0.04, extent -2.599,-2.197 -2.2,-1.803
3D body: height 0.36, standoff -0.04, extent -1.799,-2.197 -1.4,-1.803
3D body: height 0.36, standoff -0.04, extent 1.401,-2.197 1.8,-1.803
3D body: height 0.36, standoff -0.04, extent 2.201,-2.197 2.6,-1.803
3D body: height 0.36, standoff -0.04, extent 3.001,-2.197 3.4,-1.803
3D body: height 0.36, standoff -0.04, extent -3.399,-2.997 -3,-2.603
3D body: height 0.36, standoff -0.04, extent -2.599,-2.997 -2.2,-2.603
3D body: height 0.36, standoff -0.04, extent -1.799,-2.997 -1.4,-2.603
3D body: height 0.36, standoff -0.04, extent 1.401,-2.997 1.8,-2.603
3D body: height 0.36, standoff -0.04, extent 2.201,-2.997 2.6,-2.603
3D body: height 0.36, standoff -0.04, extent 3.001,-2.997 3.4,-2.603
3D body: height 0.36, standoff -0.04, extent -3.399,-3.797 -3,-3.403
3D body: height 0.36, standoff -0.04, extent -2.599,-3.797 -2.2,-3.403
3D body: height 0.36, standoff -0.04, extent -1.799,-3.797 -1.4,-3.403
3D body: height 0.36, standoff -0.04, extent 1.401,-3.797 1.8,-3.403
3D body: height 0.36, standoff -0.04, extent 2.201,-3.797 2.6,-3.403
3D body: height 0.36, standoff -0.04, extent 3.001,-3.797 3.4,-3.403
3D body: height 0.36, standoff -0.04, extent -3.399,-4.597 -3,-4.203
3D body: height 0.36, standoff -0.04, extent -2.599,-4.597 -2.2,-4.203
3D body: height 0.36, standoff -0.04, extent -1.799,-4.597 -1.4,-4.203
3D body: height 0.36, standoff -0.04, extent 1.401,-4.597 1.8,-4.203
3D body: height 0.36, standoff -0.04, extent 2.201,-4.597 2.6,-4.203
3D body: height 0.36, standoff -0.04, extent 3.001,-4.597 3.4,-4.203
3D body: height 0.36, standoff -0.04, extent -3.399,-5.397 -3,-5.003
3D body: height 0.36, standoff -0.04, extent -2.599,-5.397 -2.2,-5.003
3D body: height 0.36, standoff -0.04, extent -1.799,-5.397 -1.4,-5.003
3D body: height 0.36, standoff -0.04, extent 1.401,-5.397 1.8,-5.003
3D body: height 0.36, standoff -0.04, extent 2.201,-5.397 2.6,-5.003
3D body: height 0.36, standoff -0.04, extent 3.001,-5.397 3.4,-5.003
3D body: height 0.36, standoff -0.04, extent -3.399,-6.197 -3,-5.803
3D body: height 0.36, standoff -0.04, extent -2.599,-6.197 -2.2,-5.803
3D body: height 0.36, standoff -0.04, extent -1.799,-6.197 -1.4,-5.803
3D body: height 0.36, standoff -0.04, extent 1.401,-6.197 1.8,-5.803
3D body: height 0.36, standoff -0.04, extent 2.201,-6.197 2.6,-5.803
3D body: height 0.36, standoff -0.04, extent 3.001,-6.197 3.4,-5.803
3D body: height 1.2, standoff 0.28, extent -3.8,-6.55 3.8,6.55

## ICC_FBGA96_TBB_7P5X13_P080 [mm]
height 1.2
pads (96):
  round 0.42 smd mask+0.05: A1(-3.2,6) A2(-2.4,6) A3(-1.6,6) A7(1.6,6) A8(2.4,6) A9(3.2,6) B1(-3.2,5.2) B2(-2.4,5.2) B3(-1.6,5.2) B7(1.6,5.2) B8(2.4,5.2) B9(3.2,5.2) C1(-3.2,4.4) C2(-2.4,4.4) C3(-1.6,4.4) C7(1.6,4.4) C8(2.4,4.4) C9(3.2,4.4) D1(-3.2,3.6) D2(-2.4,3.6) D3(-1.6,3.6) D7(1.6,3.6) D8(2.4,3.6) D9(3.2,3.6) E1(-3.2,2.8) E2(-2.4,2.8) E3(-1.6,2.8) E7(1.6,2.8) E8(2.4,2.8) E9(3.2,2.8) F1(-3.2,2) F2(-2.4,2) F3(-1.6,2) F7(1.6,2) F8(2.4,2) F9(3.2,2) G1(-3.2,1.2) G2(-2.4,1.2) G3(-1.6,1.2) G7(1.6,1.2) G8(2.4,1.2) G9(3.2,1.2) H1(-3.2,0.4) H2(-2.4,0.4) H3(-1.6,0.4) H7(1.6,0.4) H8(2.4,0.4) H9(3.2,0.4) J1(-3.2,-0.4) J2(-2.4,-0.4) J3(-1.6,-0.4) J7(1.6,-0.4) J8(2.4,-0.4) J9(3.2,-0.4) K1(-3.2,-1.2) K2(-2.4,-1.2) K3(-1.6,-1.2) K7(1.6,-1.2) K8(2.4,-1.2) K9(3.2,-1.2) L1(-3.2,-2) L2(-2.4,-2) L3(-1.6,-2) L7(1.6,-2) L8(2.4,-2) L9(3.2,-2) M1(-3.2,-2.8) M2(-2.4,-2.8) M3(-1.6,-2.8) M7(1.6,-2.8) M8(2.4,-2.8) M9(3.2,-2.8) N1(-3.2,-3.6) N2(-2.4,-3.6) N3(-1.6,-3.6) N7(1.6,-3.6) N8(2.4,-3.6) N9(3.2,-3.6) P1(-3.2,-4.4) P2(-2.4,-4.4) P3(-1.6,-4.4) P7(1.6,-4.4) P8(2.4,-4.4) P9(3.2,-4.4) R1(-3.2,-5.2) R2(-2.4,-5.2) R3(-1.6,-5.2) R7(1.6,-5.2) R8(2.4,-5.2) R9(3.2,-5.2) T1(-3.2,-6) T2(-2.4,-6) T3(-1.6,-6) T7(1.6,-6) T8(2.4,-6) T9(3.2,-6)
Top Overlay:
  lines w0.12: -3.925,5.55 -3.925,6.675 -2.8,6.675 ; -0.9,-6.55 -0.9,6.55 ; 0.9,-6.55 0.9,6.55 ; -3.8,-6.55 -3.8,6.55 3.8,6.55 3.8,-6.55 -3.8,-6.55
M14-Top Assembly:
  circle w0.01: c-3.2,6 r0.4
  circle w0.01: c3.2,-0.4 r0.235
  circle w0.01: c2.4,-0.4 r0.235
  circle w0.01: c1.6,-0.4 r0.235
  circle w0.01: c-1.6,-0.4 r0.235
  circle w0.01: c-2.4,-0.4 r0.235
  circle w0.01: c-3.2,-0.4 r0.235
  circle w0.01: c3.2,-1.2 r0.235
  circle w0.01: c2.4,-1.2 r0.235
  circle w0.01: c1.6,-1.2 r0.235
  circle w0.01: c-1.6,-1.2 r0.235
  circle w0.01: c-2.4,-1.2 r0.235
  circle w0.01: c-3.2,-1.2 r0.235
  circle w0.01: c3.2,-2 r0.235
  circle w0.01: c2.4,-2 r0.235
  circle w0.01: c1.6,-2 r0.235
  circle w0.01: c-1.6,-2 r0.235
  circle w0.01: c-2.4,-2 r0.235
  circle w0.01: c-3.2,-2 r0.235
  circle w0.01: c3.2,-2.8 r0.235
  circle w0.01: c2.4,-2.8 r0.235
  circle w0.01: c1.6,-2.8 r0.235
  circle w0.01: c-1.6,-2.8 r0.235
  circle w0.01: c-2.4,-2.8 r0.235
  circle w0.01: c-3.2,-2.8 r0.235
  circle w0.01: c3.2,-3.6 r0.235
  circle w0.01: c2.4,-3.6 r0.235
  circle w0.01: c1.6,-3.6 r0.235
  circle w0.01: c-1.6,-3.6 r0.235
  circle w0.01: c-2.4,-3.6 r0.235
  circle w0.01: c-3.2,-3.6 r0.235
  circle w0.01: c3.2,-4.4 r0.235
  circle w0.01: c2.4,-4.4 r0.235
  circle w0.01: c1.6,-4.4 r0.235
  circle w0.01: c-1.6,-4.4 r0.235
  circle w0.01: c-2.4,-4.4 r0.235
  circle w0.01: c-3.2,-4.4 r0.235
  circle w0.01: c3.2,-5.2 r0.235
  circle w0.01: c2.4,-5.2 r0.235
  circle w0.01: c1.6,-5.2 r0.235
  circle w0.01: c-1.6,-5.2 r0.235
  circle w0.01: c-2.4,-5.2 r0.235
  circle w0.01: c-3.2,-5.2 r0.235
  circle w0.01: c3.2,-6 r0.235
  circle w0.01: c2.4,-6 r0.235
  circle w0.01: c1.6,-6 r0.235
  circle w0.01: c-1.6,-6 r0.235
  circle w0.01: c-2.4,-6 r0.235
  circle w0.01: c-3.2,-6 r0.235
  circle w0.01: c3.2,0.4 r0.235
  circle w0.01: c2.4,0.4 r0.235
  circle w0.01: c1.6,0.4 r0.235
  circle w0.01: c-1.6,0.4 r0.235
  circle w0.01: c-2.4,0.4 r0.235
  circle w0.01: c-3.2,0.4 r0.235
  circle w0.01: c3.2,1.2 r0.235
  circle w0.01: c2.4,1.2 r0.235
  circle w0.01: c1.6,1.2 r0.235
  circle w0.01: c-1.6,1.2 r0.235
  circle w0.01: c-2.4,1.2 r0.235
  circle w0.01: c-3.2,1.2 r0.235
  circle w0.01: c3.2,2 r0.235
  circle w0.01: c2.4,2 r0.235
  circle w0.01: c1.6,2 r0.235
  circle w0.01: c-1.6,2 r0.235
  circle w0.01: c-2.4,2 r0.235
  circle w0.01: c-3.2,2 r0.235
  circle w0.01: c3.2,2.8 r0.235
  circle w0.01: c2.4,2.8 r0.235
  circle w0.01: c1.6,2.8 r0.235
  circle w0.01: c-1.6,2.8 r0.235
  circle w0.01: c-2.4,2.8 r0.235
  circle w0.01: c-3.2,2.8 r0.235
  circle w0.01: c3.2,3.6 r0.235
  circle w0.01: c2.4,3.6 r0.235
  circle w0.01: c1.6,3.6 r0.235
  circle w0.01: c-1.6,3.6 r0.235
  circle w0.01: c-2.4,3.6 r0.235
  circle w0.01: c-3.2,3.6 r0.235
  circle w0.01: c3.2,4.4 r0.235
  circle w0.01: c2.4,4.4 r0.235
  circle w0.01: c1.6,4.4 r0.235
  circle w0.01: c-1.6,4.4 r0.235
  circle w0.01: c-2.4,4.4 r0.235
  circle w0.01: c-3.2,4.4 r0.235
  circle w0.01: c3.2,5.2 r0.235
  circle w0.01: c2.4,5.2 r0.235
  circle w0.01: c1.6,5.2 r0.235
  circle w0.01: c-1.6,5.2 r0.235
  circle w0.01: c-2.4,5.2 r0.235
  circle w0.01: c-3.2,5.2 r0.235
  circle w0.01: c3.2,6 r0.235
  circle w0.01: c2.4,6 r0.235
  circle w0.01: c1.6,6 r0.235
  circle w0.01: c-1.6,6 r0.235
  circle w0.01: c-2.4,6 r0.235
  circle w0.01: c-3.2,6 r0.235
  lines w0.01: -0.9,-6.55 -0.9,6.55 ; 0.9,-6.55 0.9,6.55 ; -3.8,-6.55 -3.8,6.55 3.8,6.55 3.8,-6.55 -3.8,-6.55
  text "'.Designator'" at 0,0 h0.75
  text "A1" at -3.55,5.8 h0.75
M16-Top Courtyard:
  lines w0.01: -4,-6.75 -4,6.75 4,6.75 4,-6.75 -4,-6.75
3D body: height 1.21, standoff 1.2, extent -3.497,5.701 -2.9,6.3
3D body: height 0.28, standoff 0.12, extent -0.9,-6.55 0.9,6.55
3D body: height 0.36, standoff -0.04, extent -3.399,5.803 -3,6.197
3D body: height 0.36, standoff -0.04, extent -2.599,5.803 -2.2,6.197
3D body: height 0.36, standoff -0.04, extent -1.799,5.803 -1.4,6.197
3D body: height 0.36, standoff -0.04, extent 1.401,5.803 1.8,6.197
3D body: height 0.36, standoff -0.04, extent 2.201,5.803 2.6,6.197
3D body: height 0.36, standoff -0.04, extent 3.001,5.803 3.4,6.197
3D body: height 0.36, standoff -0.04, extent -3.399,5.003 -3,5.397
3D body: height 0.36, standoff -0.04, extent -2.599,5.003 -2.2,5.397
3D body: height 0.36, standoff -0.04, extent -1.799,5.003 -1.4,5.397
3D body: height 0.36, standoff -0.04, extent 1.401,5.003 1.8,5.397
3D body: height 0.36, standoff -0.04, extent 2.201,5.003 2.6,5.397
3D body: height 0.36, standoff -0.04, extent 3.001,5.003 3.4,5.397
3D body: height 0.36, standoff -0.04, extent -3.399,4.203 -3,4.597
3D body: height 0.36, standoff -0.04, extent -2.599,4.203 -2.2,4.597
3D body: height 0.36, standoff -0.04, extent -1.799,4.203 -1.4,4.597
3D body: height 0.36, standoff -0.04, extent 1.401,4.203 1.8,4.597
3D body: height 0.36, standoff -0.04, extent 2.201,4.203 2.6,4.597
3D body: height 0.36, standoff -0.04, extent 3.001,4.203 3.4,4.597
3D body: height 0.36, standoff -0.04, extent -3.399,3.403 -3,3.797
3D body: height 0.36, standoff -0.04, extent -2.599,3.403 -2.2,3.797
3D body: height 0.36, standoff -0.04, extent -1.799,3.403 -1.4,3.797
3D body: height 0.36, standoff -0.04, extent 1.401,3.403 1.8,3.797
3D body: height 0.36, standoff -0.04, extent 2.201,3.403 2.6,3.797
3D body: height 0.36, standoff -0.04, extent 3.001,3.403 3.4,3.797
3D body: height 0.36, standoff -0.04, extent -3.399,2.603 -3,2.997
3D body: height 0.36, standoff -0.04, extent -2.599,2.603 -2.2,2.997
3D body: height 0.36, standoff -0.04, extent -1.799,2.603 -1.4,2.997
3D body: height 0.36, standoff -0.04, extent 1.401,2.603 1.8,2.997
3D body: height 0.36, standoff -0.04, extent 2.201,2.603 2.6,2.997
3D body: height 0.36, standoff -0.04, extent 3.001,2.603 3.4,2.997
3D body: height 0.36, standoff -0.04, extent -3.399,1.803 -3,2.197
3D body: height 0.36, standoff -0.04, extent -2.599,1.803 -2.2,2.197
3D body: height 0.36, standoff -0.04, extent -1.799,1.803 -1.4,2.197
3D body: height 0.36, standoff -0.04, extent 1.401,1.803 1.8,2.197
3D body: height 0.36, standoff -0.04, extent 2.201,1.803 2.6,2.197
3D body: height 0.36, standoff -0.04, extent 3.001,1.803 3.4,2.197
3D body: height 0.36, standoff -0.04, extent -3.399,1.003 -3,1.397
3D body: height 0.36, standoff -0.04, extent -2.599,1.003 -2.2,1.397
3D body: height 0.36, standoff -0.04, extent -1.799,1.003 -1.4,1.397
3D body: height 0.36, standoff -0.04, extent 1.401,1.003 1.8,1.397
3D body: height 0.36, standoff -0.04, extent 2.201,1.003 2.6,1.397
3D body: height 0.36, standoff -0.04, extent 3.001,1.003 3.4,1.397
3D body: height 0.36, standoff -0.04, extent -3.399,0.203 -3,0.597
3D body: height 0.36, standoff -0.04, extent -2.599,0.203 -2.2,0.597
3D body: height 0.36, standoff -0.04, extent -1.799,0.203 -1.4,0.597
3D body: height 0.36, standoff -0.04, extent 1.401,0.203 1.8,0.597
3D body: height 0.36, standoff -0.04, extent 2.201,0.203 2.6,0.597
3D body: height 0.36, standoff -0.04, extent 3.001,0.203 3.4,0.597
3D body: height 0.36, standoff -0.04, extent -3.399,-0.597 -3,-0.203
3D body: height 0.36, standoff -0.04, extent -2.599,-0.597 -2.2,-0.203
3D body: height 0.36, standoff -0.04, extent -1.799,-0.597 -1.4,-0.203
3D body: height 0.36, standoff -0.04, extent 1.401,-0.597 1.8,-0.203
3D body: height 0.36, standoff -0.04, extent 2.201,-0.597 2.6,-0.203
3D body: height 0.36, standoff -0.04, extent 3.001,-0.597 3.4,-0.203
3D body: height 0.36, standoff -0.04, extent -3.399,-1.397 -3,-1.003
3D body: height 0.36, standoff -0.04, extent -2.599,-1.397 -2.2,-1.003
3D body: height 0.36, standoff -0.04, extent -1.799,-1.397 -1.4,-1.003
3D body: height 0.36, standoff -0.04, extent 1.401,-1.397 1.8,-1.003
3D body: height 0.36, standoff -0.04, extent 2.201,-1.397 2.6,-1.003
3D body: height 0.36, standoff -0.04, extent 3.001,-1.397 3.4,-1.003
3D body: height 0.36, standoff -0.04, extent -3.399,-2.197 -3,-1.803
3D body: height 0.36, standoff -0.04, extent -2.599,-2.197 -2.2,-1.803
3D body: height 0.36, standoff -0.04, extent -1.799,-2.197 -1.4,-1.803
3D body: height 0.36, standoff -0.04, extent 1.401,-2.197 1.8,-1.803
3D body: height 0.36, standoff -0.04, extent 2.201,-2.197 2.6,-1.803
3D body: height 0.36, standoff -0.04, extent 3.001,-2.197 3.4,-1.803
3D body: height 0.36, standoff -0.04, extent -3.399,-2.997 -3,-2.603
3D body: height 0.36, standoff -0.04, extent -2.599,-2.997 -2.2,-2.603
3D body: height 0.36, standoff -0.04, extent -1.799,-2.997 -1.4,-2.603
3D body: height 0.36, standoff -0.04, extent 1.401,-2.997 1.8,-2.603
3D body: height 0.36, standoff -0.04, extent 2.201,-2.997 2.6,-2.603
3D body: height 0.36, standoff -0.04, extent 3.001,-2.997 3.4,-2.603
3D body: height 0.36, standoff -0.04, extent -3.399,-3.797 -3,-3.403
3D body: height 0.36, standoff -0.04, extent -2.599,-3.797 -2.2,-3.403
3D body: height 0.36, standoff -0.04, extent -1.799,-3.797 -1.4,-3.403
3D body: height 0.36, standoff -0.04, extent 1.401,-3.797 1.8,-3.403
3D body: height 0.36, standoff -0.04, extent 2.201,-3.797 2.6,-3.403
3D body: height 0.36, standoff -0.04, extent 3.001,-3.797 3.4,-3.403
3D body: height 0.36, standoff -0.04, extent -3.399,-4.597 -3,-4.203
3D body: height 0.36, standoff -0.04, extent -2.599,-4.597 -2.2,-4.203
3D body: height 0.36, standoff -0.04, extent -1.799,-4.597 -1.4,-4.203
3D body: height 0.36, standoff -0.04, extent 1.401,-4.597 1.8,-4.203
3D body: height 0.36, standoff -0.04, extent 2.201,-4.597 2.6,-4.203
3D body: height 0.36, standoff -0.04, extent 3.001,-4.597 3.4,-4.203
3D body: height 0.36, standoff -0.04, extent -3.399,-5.397 -3,-5.003
3D body: height 0.36, standoff -0.04, extent -2.599,-5.397 -2.2,-5.003
3D body: height 0.36, standoff -0.04, extent -1.799,-5.397 -1.4,-5.003
3D body: height 0.36, standoff -0.04, extent 1.401,-5.397 1.8,-5.003
3D body: height 0.36, standoff -0.04, extent 2.201,-5.397 2.6,-5.003
3D body: height 0.36, standoff -0.04, extent 3.001,-5.397 3.4,-5.003
3D body: height 0.36, standoff -0.04, extent -3.399,-6.197 -3,-5.803
3D body: height 0.36, standoff -0.04, extent -2.599,-6.197 -2.2,-5.803
3D body: height 0.36, standoff -0.04, extent -1.799,-6.197 -1.4,-5.803
3D body: height 0.36, standoff -0.04, extent 1.401,-6.197 1.8,-5.803
3D body: height 0.36, standoff -0.04, extent 2.201,-6.197 2.6,-5.803
3D body: height 0.36, standoff -0.04, extent 3.001,-6.197 3.4,-5.803
3D body: height 1.2, standoff 0.28, extent -3.8,-6.55 3.8,6.55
